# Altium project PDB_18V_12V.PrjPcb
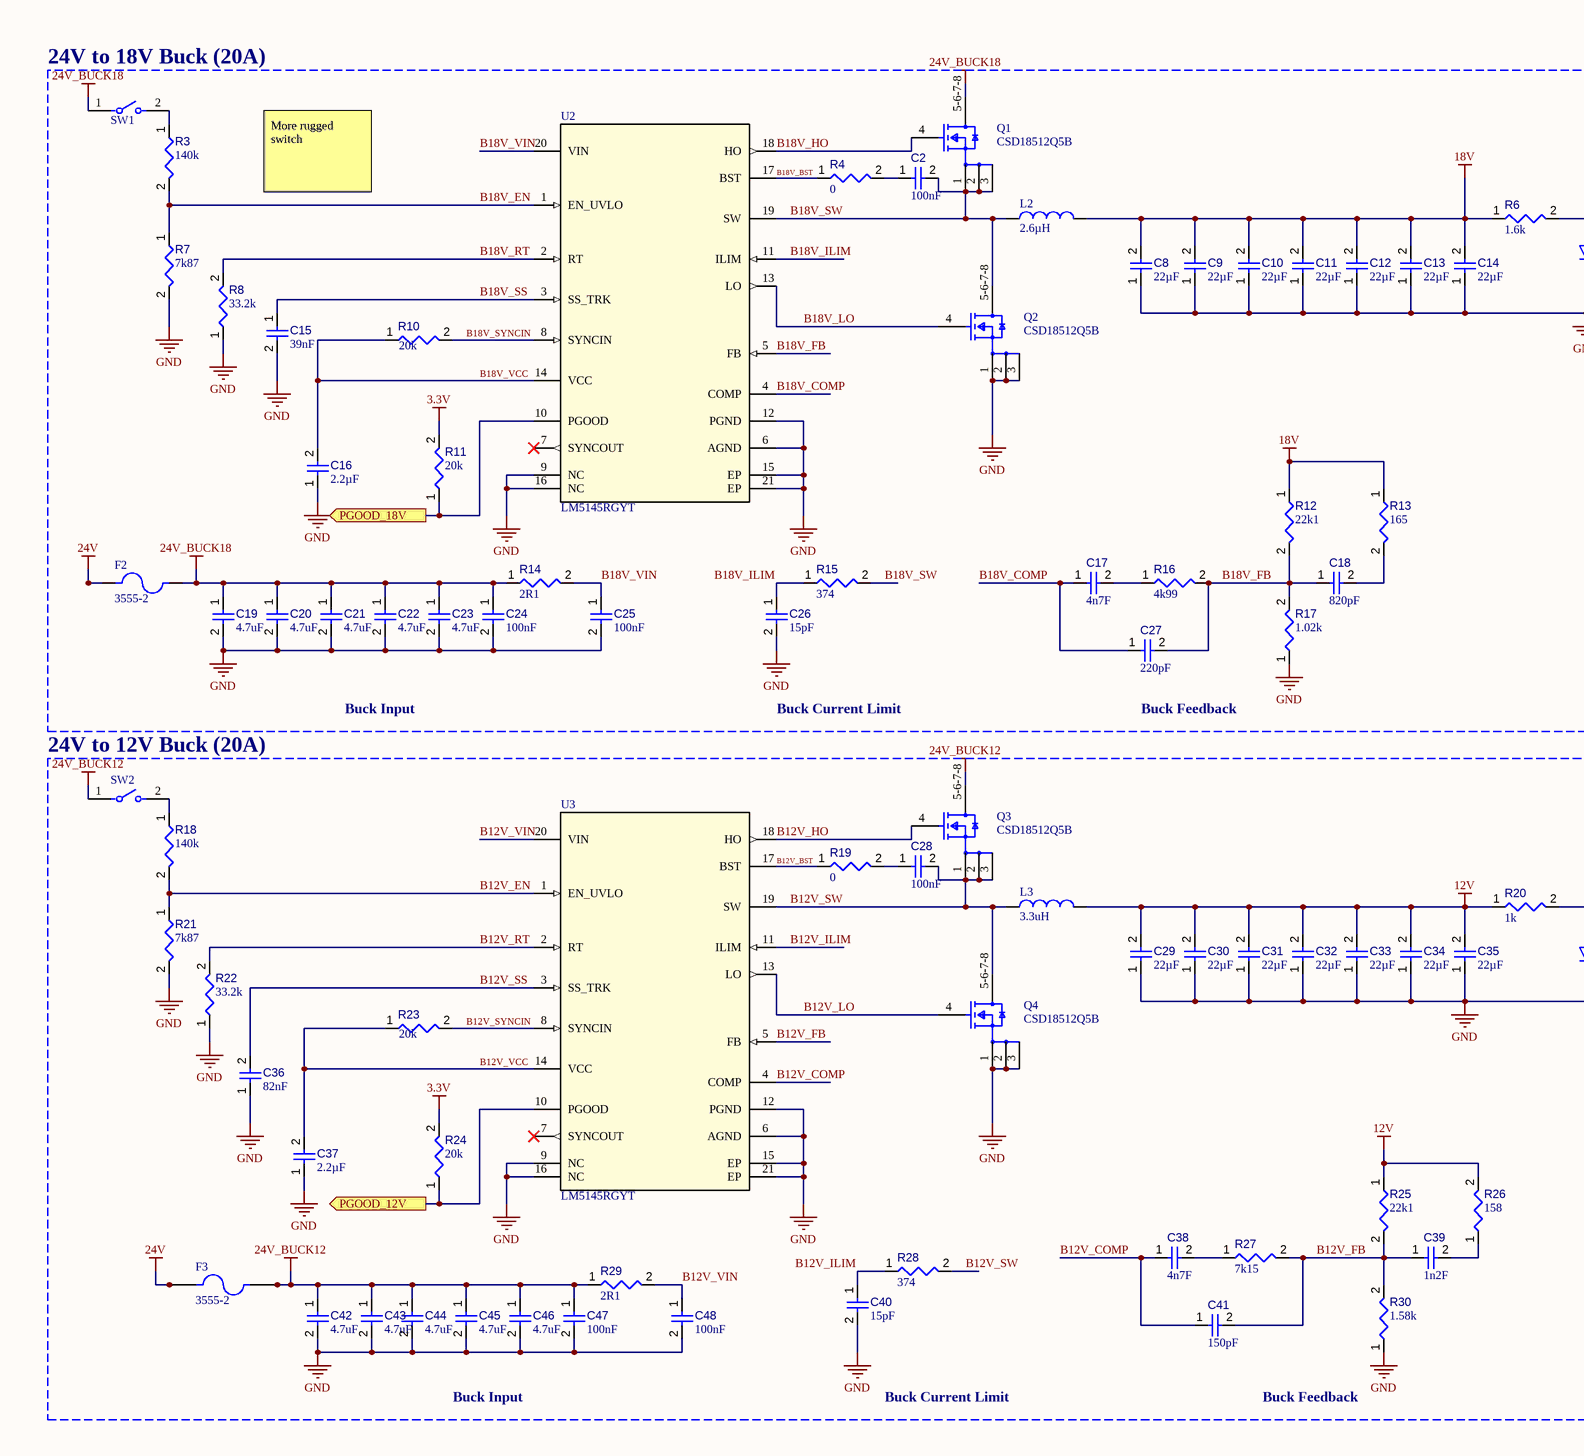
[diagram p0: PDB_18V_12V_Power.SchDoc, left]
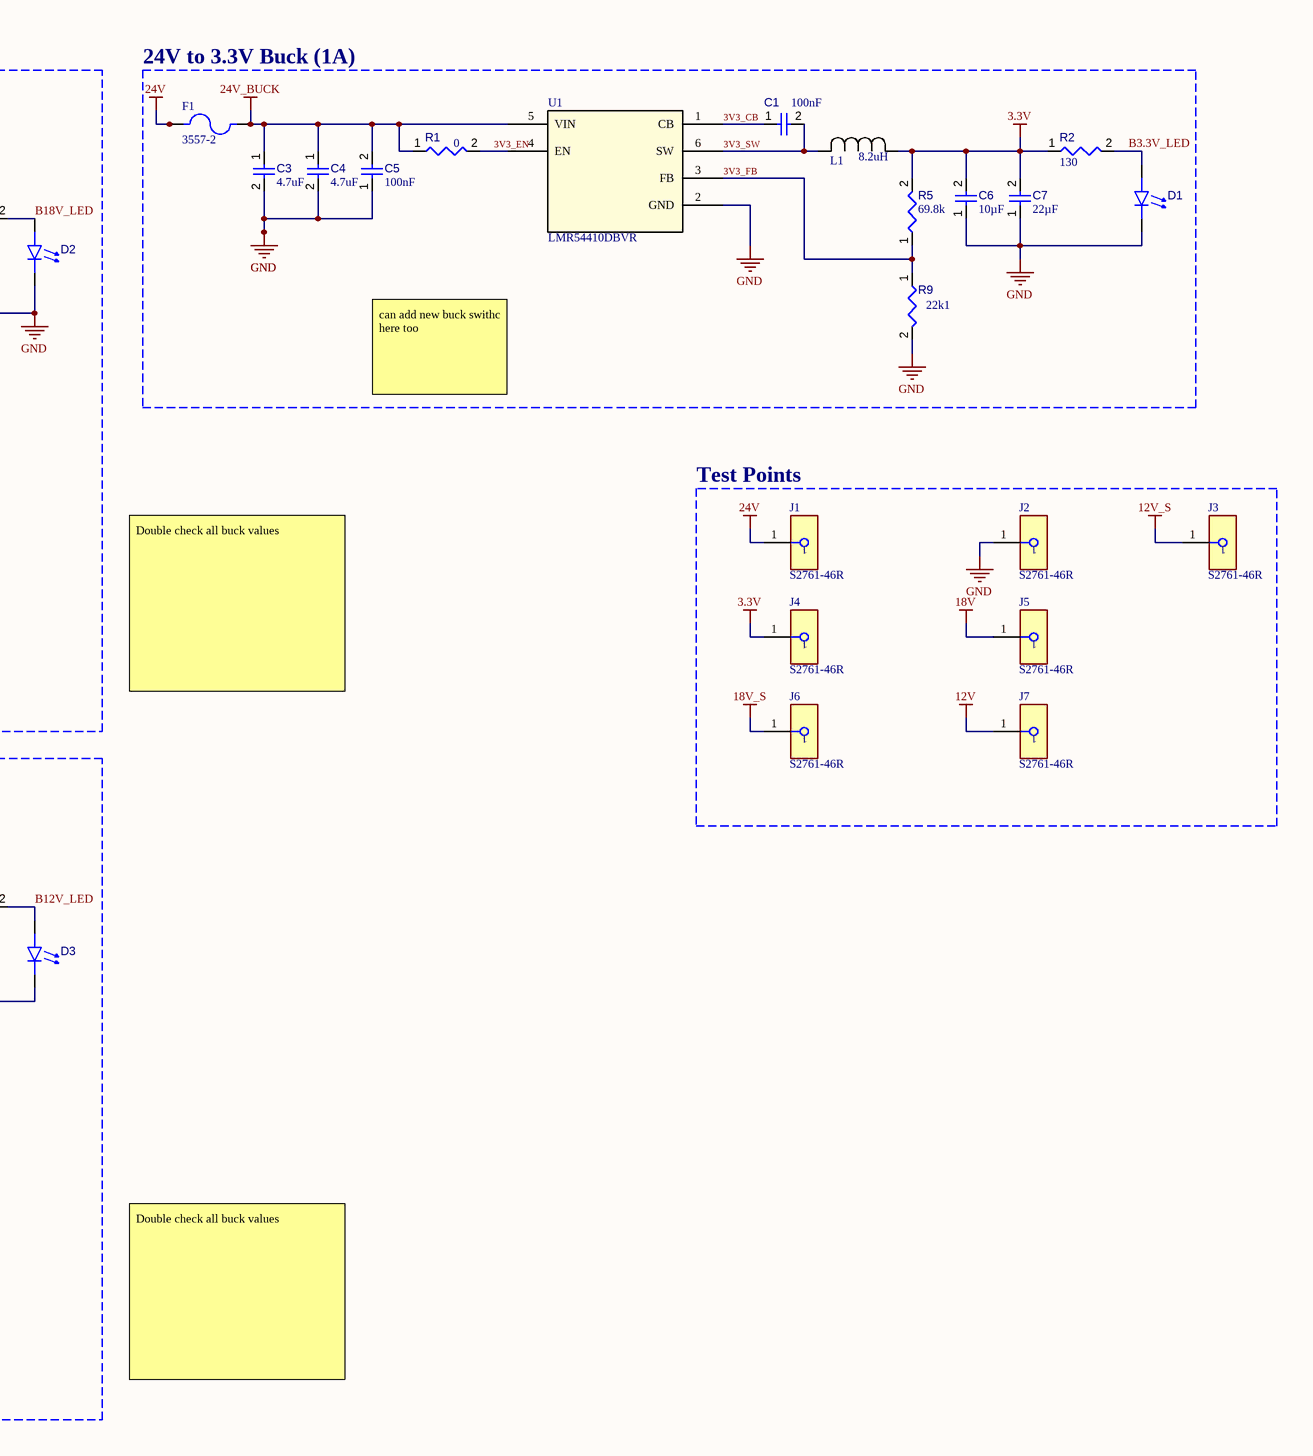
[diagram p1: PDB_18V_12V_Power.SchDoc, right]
3 sheets, 209 parts. Net scope: flat (ports and power ports of the same name join across sheets).
Board file: PDB_18V_12V.PcbDoc
Sheets:
  PDB_18V_12V_Power.SchDoc
  PDB_18V_12V_Connectors.SchDoc
  PDB_18V_12V_MCU_Peripherals.SchDoc

## Sheet PDB_18V_12V_Power.SchDoc
size A2

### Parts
C1  value 100nF  [FP-CGA3E-0_3-0_1-MFG]  (hidden comment: CGA3E3X8R1H104K080AB)
C2  value 100nF  [FP-CGA3E-0_3-0_1-MFG]  (hidden comment: CGA3E3X8R1H104K080AB)
C3  value 4.7uF  [FP-1210-L_3_3_0_4-W_2_5_0-IPC_A]  (hidden comment: 12105C475KAT2A)
C4  value 4.7uF  [FP-1210-L_3_3_0_4-W_2_5_0-IPC_A]  (hidden comment: 12105C475KAT2A)
C5  value 100nF  [FP-CGA3E-0_3-0_1-MFG]  (hidden comment: CGA3E3X8R1H104K080AB)
C6  value 10µF  [TAYO-C1210-2_M]  (hidden comment: UMK325BJ106MM-T)
C7  value 22µF  [FP-GRM32-MFG]  (hidden comment: GRM32ER61E226KE15L)
C8  value 22µF  [FP-GRM32-MFG]  (hidden comment: GRM32ER61E226KE15L)
C9  value 22µF  [FP-GRM32-MFG]  (hidden comment: GRM32ER61E226KE15L)
C10  value 22µF  [FP-GRM32-MFG]  (hidden comment: GRM32ER61E226KE15L)
C11  value 22µF  [FP-GRM32-MFG]  (hidden comment: GRM32ER61E226KE15L)
C12  value 22µF  [FP-GRM32-MFG]  (hidden comment: GRM32ER61E226KE15L)
C13  value 22µF  [FP-GRM32-MFG]  (hidden comment: GRM32ER61E226KE15L)
C14  value 22µF  [FP-GRM32-MFG]  (hidden comment: GRM32ER61E226KE15L)
C15  value 39nF  [FP-GCJ188-0_2-MFG]  (hidden comment: GCJ188R71C393KA01J)
C16  value 2.2µF  [FP-GRM188-0_1-e0_2_0_5-IPC_B]  (hidden comment: GRM188R6YA225KA12D)
C17  value 4n7F  [FP-C0603C-CF-IPC_B]  (hidden comment: C0603C472J5RACTU)
C18  value 820pF  [FP-C0603C-CF-MFG]  (hidden comment: C0603C821K5RACTU)
C19  value 4.7uF  [FP-1210-L_3_3_0_4-W_2_5_0-IPC_A]  (hidden comment: 12105C475KAT2A)
C20  value 4.7uF  [FP-1210-L_3_3_0_4-W_2_5_0-IPC_A]  (hidden comment: 12105C475KAT2A)
C21  value 4.7uF  [FP-1210-L_3_3_0_4-W_2_5_0-IPC_A]  (hidden comment: 12105C475KAT2A)
C22  value 4.7uF  [FP-1210-L_3_3_0_4-W_2_5_0-IPC_A]  (hidden comment: 12105C475KAT2A)
C23  value 4.7uF  [FP-1210-L_3_3_0_4-W_2_5_0-IPC_A]  (hidden comment: 12105C475KAT2A)
C24  value 100nF  [FP-CGA3E-0_3-0_1-MFG]  (hidden comment: CGA3E3X8R1H104K080AB)
C25  value 100nF  [FP-CGA3E-0_3-0_1-MFG]  (hidden comment: CGA3E3X8R1H104K080AB)
C26  value 15pF  [FP-0603-L_1_6_0_15-W_0_81-IPC_C]  (hidden comment: 06035A150JAT2A)
C27  value 220pF  [FP-0603-L_1_6_0_15-W_0_81-IPC_C]  (hidden comment: 06035C221KAT2A)
C28  value 100nF  [FP-CGA3E-0_3-0_1-MFG]  (hidden comment: CGA3E3X8R1H104K080AB)
C29  value 22µF  [FP-GRM32-MFG]  (hidden comment: GRM32ER61E226KE15L)
C30  value 22µF  [FP-GRM32-MFG]  (hidden comment: GRM32ER61E226KE15L)
C31  value 22µF  [FP-GRM32-MFG]  (hidden comment: GRM32ER61E226KE15L)
C32  value 22µF  [FP-GRM32-MFG]  (hidden comment: GRM32ER61E226KE15L)
C33  value 22µF  [FP-GRM32-MFG]  (hidden comment: GRM32ER61E226KE15L)
C34  value 22µF  [FP-GRM32-MFG]  (hidden comment: GRM32ER61E226KE15L)
C35  value 22µF  [FP-GRM32-MFG]  (hidden comment: GRM32ER61E226KE15L)
C36  value 82nF  [FP-GCM188-0_1-MFG]  (hidden comment: GCM188L81H823KA57J)
C37  value 2.2µF  [FP-GRM188-0_1-e0_2_0_5-IPC_B]  (hidden comment: GRM188R6YA225KA12D)
C38  value 4n7F  [FP-C0603C-CF-IPC_B]  (hidden comment: C0603C472J5RACTU)
C39  value 1n2F  [FP-CC0603-DA-IPC_B]  (hidden comment: CC0603KRX7R9BB122)
C40  value 15pF  [FP-0603-L_1_6_0_15-W_0_81-IPC_C]  (hidden comment: 06035A150JAT2A)
C41  value 150pF  [CAPC1608X90X35LL15T15]  (hidden comment: C0603C151J5GACTU)
C42  value 4.7uF  [FP-1210-L_3_3_0_4-W_2_5_0-IPC_A]  (hidden comment: 12105C475KAT2A)
C43  value 4.7uF  [FP-1210-L_3_3_0_4-W_2_5_0-IPC_A]  (hidden comment: 12105C475KAT2A)
C44  value 4.7uF  [FP-1210-L_3_3_0_4-W_2_5_0-IPC_A]  (hidden comment: 12105C475KAT2A)
C45  value 4.7uF  [FP-1210-L_3_3_0_4-W_2_5_0-IPC_A]  (hidden comment: 12105C475KAT2A)
C46  value 4.7uF  [FP-1210-L_3_3_0_4-W_2_5_0-IPC_A]  (hidden comment: 12105C475KAT2A)
C47  value 100nF  [FP-CGA3E-0_3-0_1-MFG]  (hidden comment: CGA3E3X8R1H104K080AB)
C48  value 100nF  [FP-CGA3E-0_3-0_1-MFG]  (hidden comment: CGA3E3X8R1H104K080AB)
D1  150120VS75000  [WL-SMCW_1206_150120xx75000]  (value not drawn)
D2  150120VS75000  [WL-SMCW_1206_150120xx75000]  (value not drawn)
D3  150120VS75000  [WL-SMCW_1206_150120xx75000]  (value not drawn)
F1  3557-2  [FUSE_3557-2]
F2  3555-2  [FUSE_3555-2]
F3  3555-2  [FUSE_3555-2]
J1  S2761-46R  [FP-S2761-46R-MFG]
J2  S2761-46R  [FP-S2761-46R-MFG]
J3  S2761-46R  [FP-S2761-46R-MFG]
J4  S2761-46R  [FP-S2761-46R-MFG]
J5  S2761-46R  [FP-S2761-46R-MFG]
J6  S2761-46R  [FP-S2761-46R-MFG]
J7  S2761-46R  [FP-S2761-46R-MFG]
L1  value 8.2uH  [IND_BOURNS_SRN6045]  (hidden comment: SRN6045-8R2Y)
L2  value 2.6µH  [WE-HCI_1890]  (hidden comment: 7443556260)
L3  value 3.3uH  [FP-IHLP-6767GZ-FP_3_825x1-MFG]  (hidden comment: IHLP6767GZER3R3M01)
Q1  CSD18512Q5B  [FP-DNK0008A-MFG]
Q2  CSD18512Q5B  [FP-DNK0008A-MFG]
Q3  CSD18512Q5B  [FP-DNK0008A-MFG]
Q4  CSD18512Q5B  [FP-DNK0008A-MFG]
R1  value 0  [FP-RMCF0603-IPC_A]  (hidden comment: RMCF0603ZT0R00)
R2  value 130  [FP-AC0603-MFG]  (hidden comment: AC0603FR-07130RL)
R3  value 140k  [RESC1608X55X30LL15T15]  (hidden comment: ERJ-3EKF1403V)
R4  value 0  [FP-RMCF0603-IPC_A]  (hidden comment: RMCF0603ZT0R00)
R5  value 69.8k  [FP-CRCW0603-e3-MFG]  (hidden comment: CRCW060369K8FKEB)
R6  value 1.6k  [FP-RMCF0603-MFG]  (hidden comment: RMCF0603JT1K60)
R7  value 7k87  [RESC1608X55X30NL20T20]  (hidden comment: ERA-3AEB7871V)
R8  value 33.2k  [RESC1608X55X25ML10T15]  (hidden comment: RC0603FR-0733K2L)
R9  value 22k1  [FP-RMCF0603-MFG]  (hidden comment: RMCF0603FT22K1)
R10  value 20k  [FP-RC0603-0_55-IPC_C]  (hidden comment: RC0603FR-0720KL)
R11  value 20k  [FP-RC0603-0_55-IPC_C]  (hidden comment: RC0603FR-0720KL)
R12  value 22k1  [FP-RMCF0603-MFG]  (hidden comment: RMCF0603FT22K1)
R13  value 165  [RESC1608X55X30LL15T15]  (hidden comment: ERJ-3EKF1650V)
R14  value 2R1  [FP-CRCW0603-e3-MFG]  (hidden comment: CRCW06032R10FKEA)
R15  value 374  [RESC1608X55X25LL10T15]  (hidden comment: RC0603FR-07374RL)
R16  value 4k99  [FP-RT0603-IPC_C]  (hidden comment: RT0603DRD074K99L)
R17  value 1.02k  [RESC1609X50X30LL10T20]  (hidden comment: CRCW06031K02FKEA)
R18  value 140k  [RESC1608X55X30LL15T15]  (hidden comment: ERJ-3EKF1403V)
R19  value 0  [FP-RMCF0603-IPC_A]  (hidden comment: RMCF0603ZT0R00)
R20  value 1k  [RESC1608X55X25ML10T15]  (hidden comment: RT0603BRE071KL)
R21  value 7k87  [RESC1608X55X30NL20T20]  (hidden comment: ERA-3AEB7871V)
R22  value 33.2k  [RESC1608X55X25ML10T15]  (hidden comment: RC0603FR-0733K2L)
R23  value 20k  [FP-RC0603-0_55-IPC_C]  (hidden comment: RC0603FR-0720KL)
R24  value 20k  [FP-RC0603-0_55-IPC_C]  (hidden comment: RC0603FR-0720KL)
R25  value 22k1  [FP-RMCF0603-MFG]  (hidden comment: RMCF0603FT22K1)
R26  value 158  [RESC1608X55X25LL10T15]  (hidden comment: RC0603FR-07158RL)
R27  value 7k15  [FP-CRCW0603-HPe3-MFG]  (hidden comment: CRCW06037K15FKEAHP)
R28  value 374  [RESC1608X55X25LL10T15]  (hidden comment: RC0603FR-07374RL)
R29  value 2R1  [FP-CRCW0603-e3-MFG]  (hidden comment: CRCW06032R10FKEA)
R30  value 1.58k  [RESC1609X50X30LL10T20]  (hidden comment: CRCW06031K58FKEA)
SW1  SDA01H1SBD  [FP-SDA01H1SBD-MFG]  (value not drawn)
SW2  SDA01H1SBD  [FP-SDA01H1SBD-MFG]  (value not drawn)
U1  LMR54410DBVR  [SOT-23-6-DBV_TEX]
U2  LM5145RGYT  [RGY0020B]
U3  LM5145RGYT  [RGY0020B]

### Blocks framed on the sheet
24V to 18V Buck (20A): C2 C8-C27 D2 F2 L2 Q1 Q2 R3 R4 R6-R8 R10-R17 SW1 U2
24V to 3.3V Buck (1A): C1 C3-C7 D1 F1 L1 R1 R2 R5 R9 U1
Test Points: J1-J7
24V to 12V Buck (20A): C28-C48 D3 F3 L3 Q3 Q4 R18-R30 SW2 U3

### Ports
PGOOD_12V (out), PGOOD_18V (out)

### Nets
3.3V: C6.2 C7.2 J4.1 L1.1 R2.1 R5.2 R11.2 R24.2
12V: C29.2 C30.2 C31.2 C32.2 C33.2 C34.2 C35.2 J7.1 L3.2 R20.1 R25.1 R26.2
12V_S: J3.1
18V: C8.2 C9.2 C10.2 C11.2 C12.2 C13.2 C14.2 J5.1 L2.2 R6.1 R12.1 R13.1
18V_S: J6.1
24V: F1.1_1 F1.1_2 F2.1_1 F2.1_2 F3.1_1 F3.1_2 J1.1
24V_BUCK: C3.1 C4.1 C5.2 F1.2_1 F1.2_2 R1.1 U1.5(VIN)
24V_BUCK12: C42.1 C43.1 C44.1 C45.1 C46.1 C47.1 F3.2_1 F3.2_2 Q3.5-6-7-8(D) R29.1 SW2.1
24V_BUCK18: C19.1 C20.1 C21.1 C22.1 C23.1 C24.1 F2.2_1 F2.2_2 Q1.5-6-7-8(D) R14.1 SW1.1
GND: C3.2 C4.2 C5.1 C6.1 C7.1 C8.1 C9.1 C10.1 C11.1 C12.1 C13.1 C14.1 C15.2 C16.1 C19.2 C20.2 C21.2 C22.2 C23.2 C24.2 C25.2 C26.2 C29.1 C30.1 C31.1 C32.1 C33.1 C34.1 C35.1 C36.1 C37.1 C40.2 C42.2 C43.2 C44.2 C45.2 C46.2 C47.2 C48.2 D1.1(K) D2.1(K) D3.1(K) J2.1 Q2.1(S) Q2.2(S) Q2.3(S) Q4.1(S) Q4.2(S) Q4.3(S) R7.2 R8.1 R9.2 R17.1 R21.2 R22.1 R30.1 U1.2(GND) U2.6(AGND) U2.9(NC) U2.12(PGND) U2.15(EP) U2.16(NC) U2.21(EP) U3.6(AGND) U3.9(NC) U3.12(PGND) U3.15(EP) U3.16(NC) U3.21(EP)
3V3_CB: C1.1 U1.1(CB)
3V3_EN: R1.2 U1.4(EN)
3V3_FB: R5.1 R9.1 U1.3(FB)
3V3_SW: C1.2 L1.2 U1.6(SW)
B3.3V_LED: D1.2(A) R2.2
B12V_BST: R19.1 U3.17(BST)
B12V_COMP: C38.1 C41.1 U3.4(COMP)
B12V_EN: R18.2 R21.1 U3.1(EN_UVLO)
B12V_FB: C39.1 C41.2 R25.2 R27.2 R30.2 U3.5(FB)
B12V_HO: Q3.4(G) U3.18(HO)
B12V_ILIM: C40.1 R28.1 U3.11(ILIM)
B12V_LED: D3.2(A) R20.2
B12V_LO: Q4.4(G) U3.13(LO)
B12V_RT: R22.2 U3.2(RT)
B12V_SS: C36.2 U3.3(SS_TRK)
B12V_SW: C28.2 L3.1 Q3.1(S) Q3.2(S) Q3.3(S) Q4.5-6-7-8(D) R28.2 U3.19(SW)
B12V_SYNCIN: R23.2 U3.8(SYNCIN)
B12V_VCC: C37.2 R23.1 U3.14(VCC)
B12V_VIN: C48.1 R29.2 U3.20(VIN)
B18V_BST: R4.1 U2.17(BST)
B18V_COMP: C17.1 C27.1 U2.4(COMP)
B18V_EN: R3.2 R7.1 U2.1(EN_UVLO)
B18V_FB: C18.1 C27.2 R12.2 R16.2 R17.2 U2.5(FB)
B18V_HO: Q1.4(G) U2.18(HO)
B18V_ILIM: C26.1 R15.1 U2.11(ILIM)
B18V_LED: D2.2(A) R6.2
B18V_LO: Q2.4(G) U2.13(LO)
B18V_RT: R8.2 U2.2(RT)
B18V_SS: C15.1 U2.3(SS_TRK)
B18V_SW: C2.2 L2.1 Q1.1(S) Q1.2(S) Q1.3(S) Q2.5-6-7-8(D) R15.2 U2.19(SW)
B18V_SYNCIN: R10.2 U2.8(SYNCIN)
B18V_VCC: C16.2 R10.1 U2.14(VCC)
B18V_VIN: C25.1 R14.2 U2.20(VIN)
PGOOD_12V: R24.1 U3.10(PGOOD) ; port PGOOD_12V
PGOOD_18V: R11.1 U2.10(PGOOD) ; port PGOOD_18V
NetC2_1: C2.1 R4.2
NetC17_2: C17.2 R16.1
NetC18_2: C18.2 R13.2
NetC28_1: C28.1 R19.2
NetC38_2: C38.2 R27.1
NetC39_2: C39.2 R26.1
NetR3_1: R3.1 SW1.2
NetR18_1: R18.1 SW2.2

Not connected (* = marked no-connect by the designer): U2 7(SYNCOUT)*; U3 7(SYNCOUT)*

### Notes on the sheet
- More rugged switch
- can add new buck swithc here too
- Buck Input
- Buck Current Limit
- Buck Feedback
- Double check all buck values

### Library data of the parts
C1 C2 C5 C24 C25 C28 C47 C48 = CMP-001-00163-1: CGA Series 0603 0.1 uF 50 V ±10% Tolerance X8R Multilayer Ceramic Capacitor; Voltage Rating: 50V
C3 C4 C19-C23 C42-C46 = CMP-001-00137-1: Ceramic Capacitor, Multilayer, Ceramic, 50V, 10% +Tol, 10% -Tol, X7R, 15% TC, 4.7uF, Surface Mount, 1210
C6 = CMP-001-00183-1: 50V 10uF X5R ±20% 1210 Multilayer Ceramic Capacitors MLCC - SMD/SMT ROHS
C7-C14 C29-C35 = CMP-001-00168-1: 25V 22uF X5R ±10% 1210 Multilayer Ceramic Capacitors MLCC - SMD/SMT ROHS
C15 = CMP-001-00170-1: Ceramic Capacitor, YES, Ceramic, 16V, 10% +Tol, 10% -Tol, X7R, 15% TC, 0.039uF, Surface Mount, 1608M/0603
C16 C37 = CMP-001-00153-1: Ceramic Capacitor, Multilayer, Ceramic, 35V, 10% +Tol, 10% -Tol, X5R, 15% TC, 2.2uF, Surface Mount, 0603
C17 C38 = CMP-001-00143-1: Ceramic Capacitor, Multilayer, Ceramic, 50V, 5% +Tol, 5% -Tol, X7R, 15% TC, 0.0047uF, Surface Mount, 0603
C18 = CMP-001-00171-1: C0603C 820PF Ceramic Multilayer Capacitor, 50 VDC, +125DEGC, X7R Dielec, +/-10%; Voltage Rating: 50V; Tolerance: 10%
C26 C40 = CMP-001-00146-1: Ceramic Capacitor, Multilayer, Ceramic, 50V, 5% +Tol, 5% -Tol, C0G, 30ppm/Cel TC, 0.000015uF, Surface Mount, 0603
C27 = CMP-001-00148-1: Ceramic Capacitor, Multilayer, Ceramic, 50V, 10% +Tol, 10% -Tol, X7R, 15% TC, 0.00022uF, Surface Mount, 0603
C36 = CMP-001-00182-1: Ceramic Capacitor, YES, Ceramic, 50V, 10% +Tol, 10% -Tol, X8L, -40/+15% TC, 0.082uF, Surface Mount, 1608M/0603
C39 = CMP-001-00145-1: Ceramic Capacitor, Multilayer, Ceramic, 50V, 10% +Tol, 10% -Tol, X7R, 15% TC, 0.0012uF, Surface Mount, 0603
C41 = CMP-001-00144-1: Ceramic Capacitor, Multilayer, Ceramic, 50V, 5% +Tol, 5% -Tol, C0G, 30ppm/Cel TC, 0.00015uF, Surface Mount, 0603
D1-D3 = CMP-007-00044-1: Single Color LED, Bright Green, Water Clear, 2mm; Forward Current: 30mA
F1 = CMP-005-00014-1: THM 2 in 1 Auto Blade Holder; MF: Keystone Electronics
F2 F3 = CMP-005-00015-2: Auto Fuse Holder, 1 Fuse, Blade, Standard, THM, 50Amp, Hi-Temp Nylon, UL94V-0; MF: Keystone Electronics
J1-J7 = CMP-002-00083-1: Interconnection Device
L1 = CMP-006-00036-1: Description; Manufacturer_Name: Bourns Electronics
L2 = CMP-006-00034-1: WE-HCI SMT Flat Wire High Current Inductor; Tolerance: 20%; Current Rating: 31.5A; Self Resonant Frequency: 42MHz
L3 = CMP-006-00032-1: Inductor High Current Shielded Wirewound 3.3uH 20% 100KHz 28A 3.88mOhm DCR 6767 T/R
Q1-Q4 = CMP-013-00041-1: 40-V, N channel NexFET™ power MOSFET, single SON 5 mm x 6 mm, 1.6 mOhm 8-VSON-CLIP -55 to 150
R1 R4 R19 = CMP-009-00236-1: Fixed Resistor, Metal Glaze/thick Film, 0.1W, 0ohm, Surface Mount, 0603; Power: 100mW
R2 = CMP-009-00292-1: Res Thick Film 0603 130 Ohm 1% 0.1W(1/10W) ±100ppm/C Pad SMD T/R Automotive AEC-Q200; Voltage Rating: 75V
R3 R18 = CMP-009-00259-1: Fixed Resistor, Metal Glaze/thick Film, 0.1W, 140000ohm, 75V, 1% +/-Tol, 100ppm/Cel, Surface Mount, 0603; Power: 100mW
R5 = CMP-009-00297-1: CRCW FIXED RESISTOR 0603 (1608Metric) Chip Resistor ±1% ±100ppm/C 69.8kOhm 0.1W 1/10W; Voltage Rating: 75V
R6 = CMP-009-00285-1: Res Thick Film 0603 1.6K Ohm 5% 1/10W ±200ppm/°C Molded SMD Paper T/R; Voltage Rating: 75V
R7 R21 = CMP-009-00260-1: Fixed Resistor, Thin Film, 0.1W, 7870ohm, 75V, 0.1% +/-Tol, 25ppm/Cel, Surface Mount, 0603; Power: 100mW
R8 R22 = CMP-009-00279-1: 100mW Thick Film Resistors 75V ±100ppm/℃ ±1% 33.2kΩ 0603 Chip Resistor - Surface Mount ROHS
R9 R12 R25 = CMP-009-00240-1: Fixed Resistor, Metal Glaze/thick Film, 0.1W, 22100ohm, 75V, 1% +/-Tol, 100ppm/Cel, Surface Mount, 0603; Power: 100mW
R10 R11 R23 R24 = CMP-009-00212-1: Fixed Resistor, Metal Glaze/thick Film, 0.1W, 20000ohm, 75V, 1% +/-Tol, 100ppm/Cel, Surface Mount, 0603; Power: 100mW
R13 = CMP-009-00251-1: Fixed Resistor, Metal Glaze/thick Film, 0.1W, 165ohm, 75V, 1% +/-Tol, 100ppm/Cel, Surface Mount, 0603; Power: 100mW
R14 R29 = CMP-009-00275-1: Res Thick Film 0603 2.1 Ohm 1% 0.1W(1/10W) ±100ppm/C Molded SMD Automotive Paper T/R; Voltage Rating: 75V
R15 R28 = CMP-009-00283-1: Res Thick Film 0603 374 Ohm 1% 0.1W(1/10W) ±100ppm/C Pad SMD T/R; Voltage Rating: 75V
R16 = CMP-009-00250-1: Fixed Resistor, Thin Film, 0.1W, 4990ohm, 75V, 0.5% +/-Tol, 25ppm/Cel, Surface Mount, 0603; Power: 100mW
R17 = CMP-009-00284-1: Res Thick Film 0603 1.02K Ohm 1% 1/10W ±100ppm/°C Molded SMD SMD Paper T/R; Voltage Rating: 75V
R20 = CMP-009-00263-1: Fixed Resistor, Thin Film, 0.1W, 1000ohm, 75V, 0.1% +/-Tol, 50ppm/Cel, Surface Mount, 0603; Power: 100mW
R26 = CMP-009-00287-1: Res Thick Film 0603 158 Ohm 1% 0.1W(1/10W) ±100ppm/C Pad SMD T/R; Voltage Rating: 75V
R27 = CMP-009-00197-1: Fixed Resistor, Metal Glaze/thick Film, 0.33W, 7150ohm, 75V, 1% +/-Tol, 100ppm/Cel, Surface Mount, 0603; Power: 250mW
R30 = CMP-009-00286-1: Fixed Resistor, Metal Glaze/Thick Film, 0.1W, 1580ohm, 75V, 1% +/-Tol, Surface Mount, 0603
SW1 SW2 = CMP-011-00016-1: Slide Dip Switch, 1 Switches, SPST, Latched, 0.1A, 50VDC, Solder Terminal, Surface Mount-straight
U1 = CMP-00030-00008-3: 4V to 36V, 1A, 80-ÂµA Iq synchronous SIMPLE SWITCHERÂ® power converter 6-SOT-23 -40 to 125; Manufacturer_Name: Texas Instruments
U2 U3 = CMP-049-000000-3: 75V Synchronous Buck Controller With Wide Input Voltage and Duty Cycle Ranges 20-VQFN -40 to 125; Manufacturer_Name: Texas Instruments

## Sheet PDB_18V_12V_Connectors.SchDoc
size A3
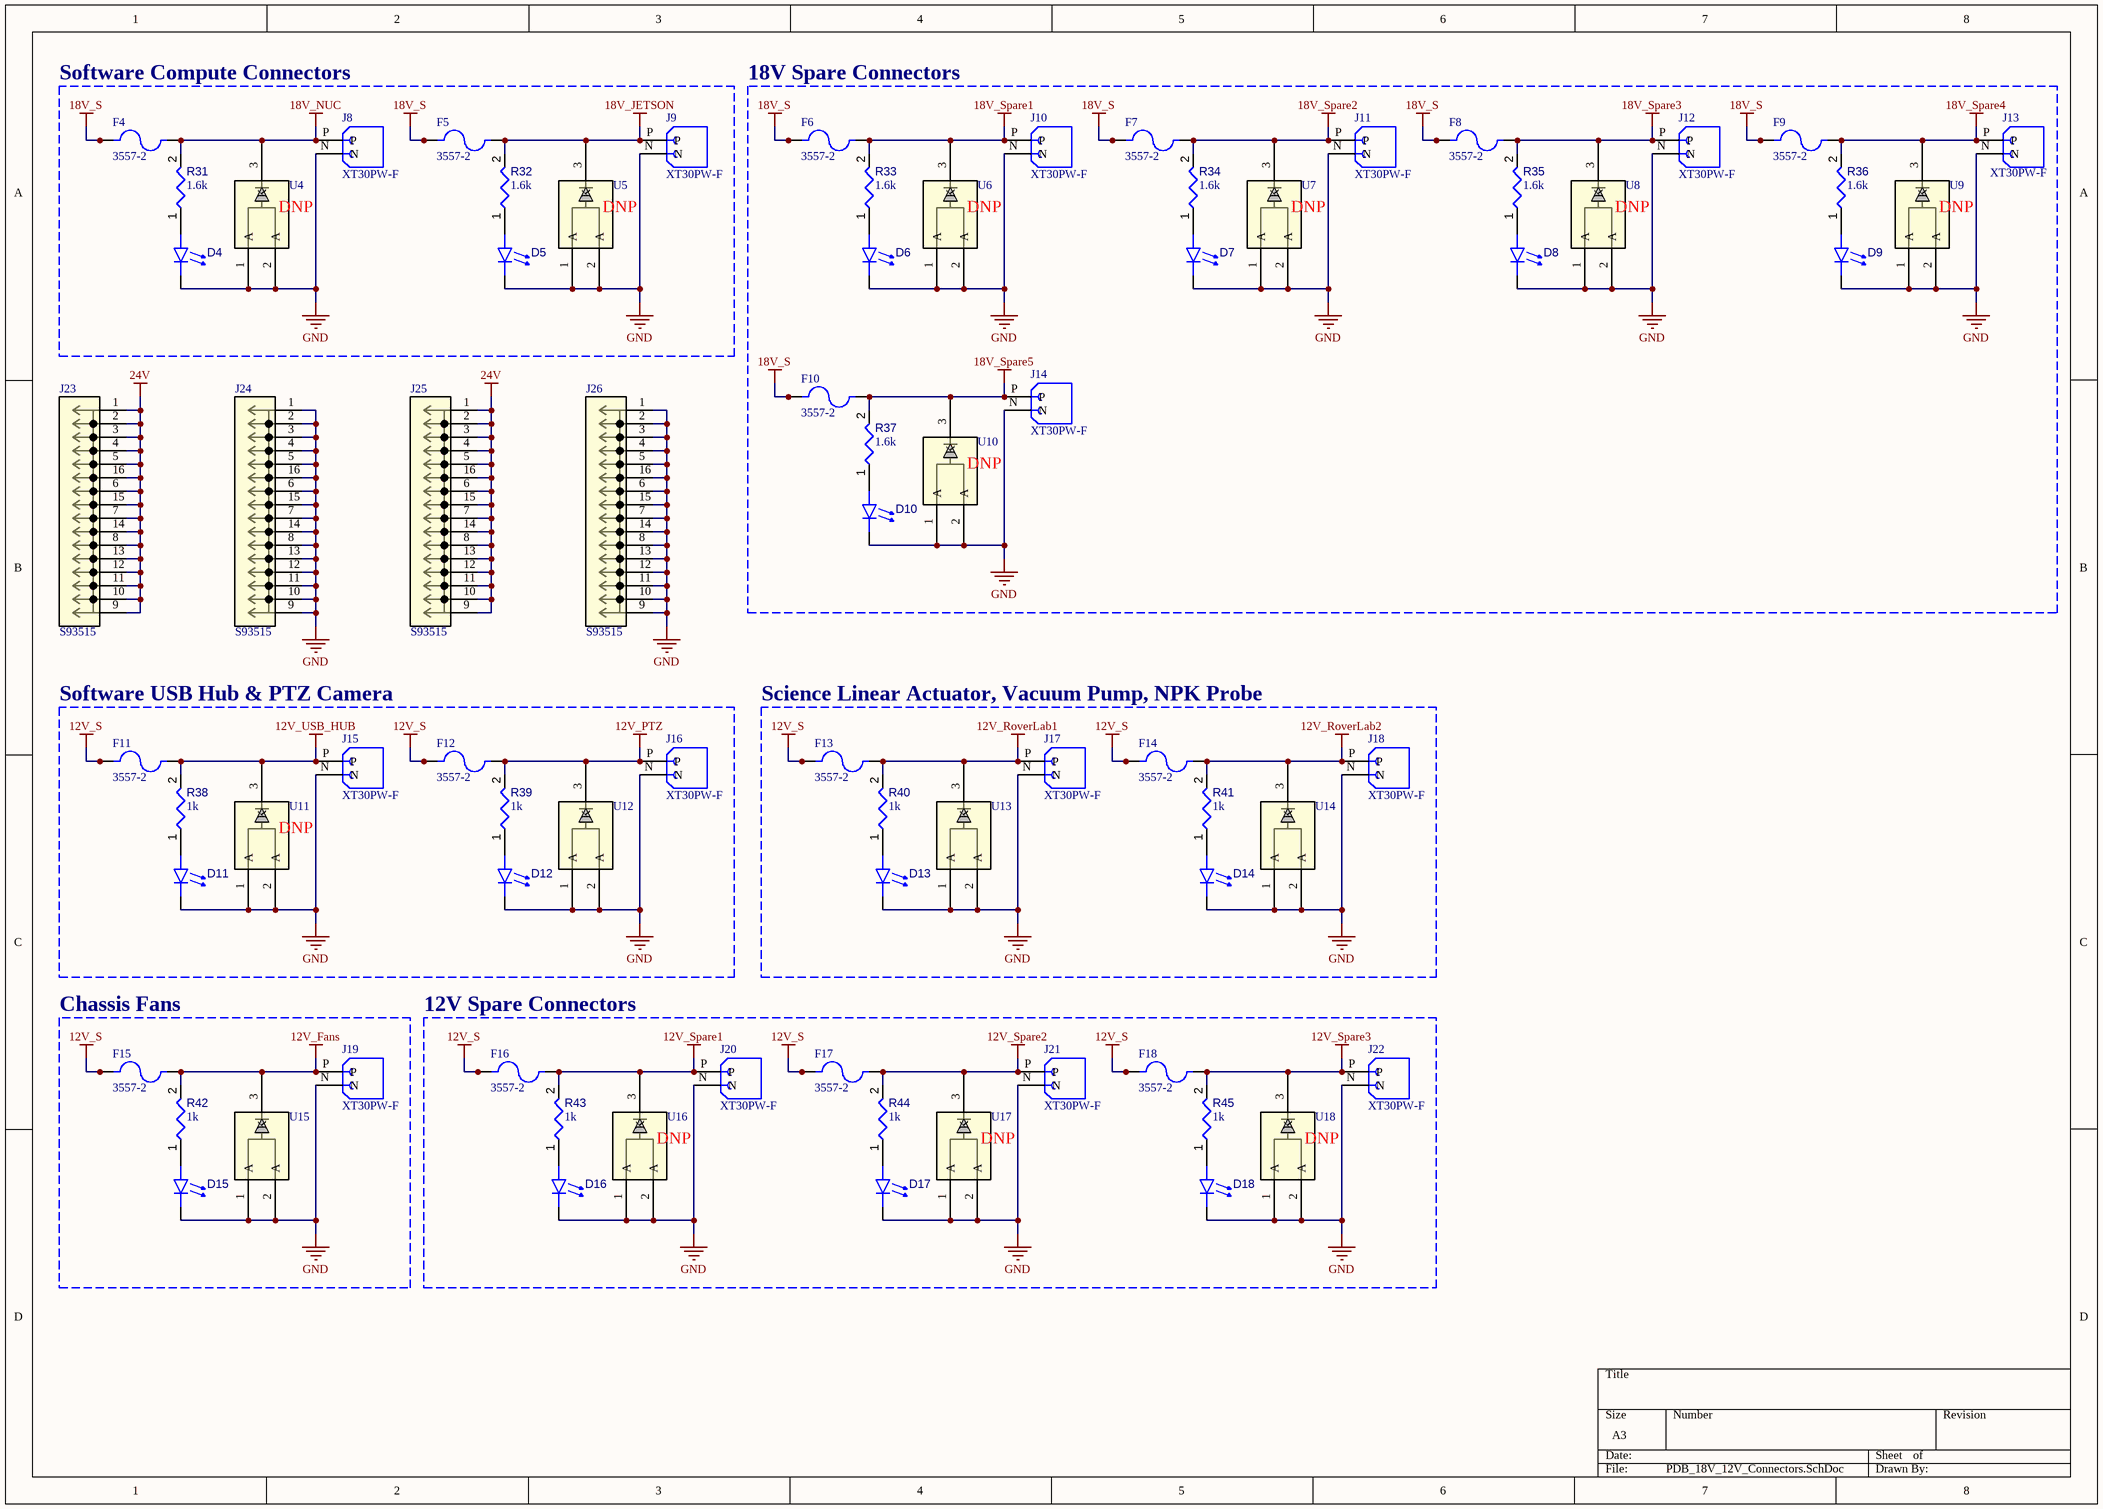
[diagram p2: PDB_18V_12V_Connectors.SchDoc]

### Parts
D4  150120VS75000  [WL-SMCW_1206_150120xx75000]  (value not drawn)
D5  150120VS75000  [WL-SMCW_1206_150120xx75000]  (value not drawn)
D6  150120VS75000  [WL-SMCW_1206_150120xx75000]  (value not drawn)
D7  150120VS75000  [WL-SMCW_1206_150120xx75000]  (value not drawn)
D8  150120VS75000  [WL-SMCW_1206_150120xx75000]  (value not drawn)
D9  150120VS75000  [WL-SMCW_1206_150120xx75000]  (value not drawn)
D10  150120VS75000  [WL-SMCW_1206_150120xx75000]  (value not drawn)
D11  150120VS75000  [WL-SMCW_1206_150120xx75000]  (value not drawn)
D12  150120VS75000  [WL-SMCW_1206_150120xx75000]  (value not drawn)
D13  150120VS75000  [WL-SMCW_1206_150120xx75000]  (value not drawn)
D14  150120VS75000  [WL-SMCW_1206_150120xx75000]  (value not drawn)
D15  150120VS75000  [WL-SMCW_1206_150120xx75000]  (value not drawn)
D16  150120VS75000  [WL-SMCW_1206_150120xx75000]  (value not drawn)
D17  150120VS75000  [WL-SMCW_1206_150120xx75000]  (value not drawn)
D18  150120VS75000  [WL-SMCW_1206_150120xx75000]  (value not drawn)
F4  3557-2  [FUSE_3557-2]
F5  3557-2  [FUSE_3557-2]
F6  3557-2  [FUSE_3557-2]
F7  3557-2  [FUSE_3557-2]
F8  3557-2  [FUSE_3557-2]
F9  3557-2  [FUSE_3557-2]
F10  3557-2  [FUSE_3557-2]
F11  3557-2  [FUSE_3557-2]
F12  3557-2  [FUSE_3557-2]
F13  3557-2  [FUSE_3557-2]
F14  3557-2  [FUSE_3557-2]
F15  3557-2  [FUSE_3557-2]
F16  3557-2  [FUSE_3557-2]
F17  3557-2  [FUSE_3557-2]
F18  3557-2  [FUSE_3557-2]
J8  XT30PW-F  [AMASS_XT30PW-F]
J9  XT30PW-F  [AMASS_XT30PW-F]
J10  XT30PW-F  [AMASS_XT30PW-F]
J11  XT30PW-F  [AMASS_XT30PW-F]
J12  XT30PW-F  [AMASS_XT30PW-F]
J13  XT30PW-F  [AMASS_XT30PW-F]
J14  XT30PW-F  [AMASS_XT30PW-F]
J15  XT30PW-F  [AMASS_XT30PW-F]
J16  XT30PW-F  [AMASS_XT30PW-F]
J17  XT30PW-F  [AMASS_XT30PW-F]
J18  XT30PW-F  [AMASS_XT30PW-F]
J19  XT30PW-F  [AMASS_XT30PW-F]
J20  XT30PW-F  [AMASS_XT30PW-F]
J21  XT30PW-F  [AMASS_XT30PW-F]
J22  XT30PW-F  [AMASS_XT30PW-F]
J23  S93515  [CONN16_S93515_WRE]
J24  S93515  [CONN16_S93515_WRE]
J25  S93515  [CONN16_S93515_WRE]
J26  S93515  [CONN16_S93515_WRE]
R31  value 1.6k  [FP-RMCF0603-MFG]  (hidden comment: RMCF0603JT1K60)
R32  value 1.6k  [FP-RMCF0603-MFG]  (hidden comment: RMCF0603JT1K60)
R33  value 1.6k  [FP-RMCF0603-MFG]  (hidden comment: RMCF0603JT1K60)
R34  value 1.6k  [FP-RMCF0603-MFG]  (hidden comment: RMCF0603JT1K60)
R35  value 1.6k  [FP-RMCF0603-MFG]  (hidden comment: RMCF0603JT1K60)
R36  value 1.6k  [FP-RMCF0603-MFG]  (hidden comment: RMCF0603JT1K60)
R37  value 1.6k  [FP-RMCF0603-MFG]  (hidden comment: RMCF0603JT1K60)
R38  value 1k  [RESC1608X55X25ML10T15]  (hidden comment: RT0603BRE071KL)
R39  value 1k  [RESC1608X55X25ML10T15]  (hidden comment: RT0603BRE071KL)
R40  value 1k  [RESC1608X55X25ML10T15]  (hidden comment: RT0603BRE071KL)
R41  value 1k  [RESC1608X55X25ML10T15]  (hidden comment: RT0603BRE071KL)
R42  value 1k  [RESC1608X55X25ML10T15]  (hidden comment: RT0603BRE071KL)
R43  value 1k  [RESC1608X55X25ML10T15]  (hidden comment: RT0603BRE071KL)
R44  value 1k  [RESC1608X55X25ML10T15]  (hidden comment: RT0603BRE071KL)
R45  value 1k  [RESC1608X55X25ML10T15]  (hidden comment: RT0603BRE071KL)
U4  SDT30B100D1-13  [TO252_DIO]  (value not drawn)
U5  SDT30B100D1-13  [TO252_DIO]  (value not drawn)
U6  SDT30B100D1-13  [TO252_DIO]  (value not drawn)
U7  SDT30B100D1-13  [TO252_DIO]  (value not drawn)
U8  SDT30B100D1-13  [TO252_DIO]  (value not drawn)
U9  SDT30B100D1-13  [TO252_DIO]  (value not drawn)
U10  SDT30B100D1-13  [TO252_DIO]  (value not drawn)
U11  SDT30B100D1-13  [TO252_DIO]  (value not drawn)
U12  SDT30B100D1-13  [TO252_DIO]  (value not drawn)
U13  SDT30B100D1-13  [TO252_DIO]  (value not drawn)
U14  SDT30B100D1-13  [TO252_DIO]  (value not drawn)
U15  SDT30B100D1-13  [TO252_DIO]  (value not drawn)
U16  SDT30B100D1-13  [TO252_DIO]  (value not drawn)
U17  SDT30B100D1-13  [TO252_DIO]  (value not drawn)
U18  SDT30B100D1-13  [TO252_DIO]  (value not drawn)

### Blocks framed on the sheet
Software Compute Connectors: D4 D5 F4 F5 J8 J9 R31 R32 U4 U5
18V Spare Connectors: D6-D10 F6-F10 J10-J14 R33-R37 U6-U10
Software USB Hub & PTZ Camera: D11 D12 F11 F12 J15 J16 R38 R39 U11 U12
Science Linear Actuator, Vacuum Pump, NPK Probe: D13 D14 F13 F14 J17 J18 R40 R41 U13 U14
Chassis Fans: D15 F15 J19 R42 U15
12V Spare Connectors: D16-D18 F16-F18 J20-J22 R43-R45 U16-U18

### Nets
12V_Fans: F15.2_1 F15.2_2 J19.P R42.2 U15.3(K)
12V_PTZ: F12.2_1 F12.2_2 J16.P R39.2 U12.3(K)
12V_RoverLab1: F13.2_1 F13.2_2 J17.P R40.2 U13.3(K)
12V_RoverLab2: F14.2_1 F14.2_2 J18.P R41.2 U14.3(K)
12V_S: F11.1_1 F11.1_2 F12.1_1 F12.1_2 F13.1_1 F13.1_2 F14.1_1 F14.1_2 F15.1_1 F15.1_2 F16.1_1 F16.1_2 F17.1_1 F17.1_2 F18.1_1 F18.1_2
12V_Spare1: F16.2_1 F16.2_2 J20.P R43.2 U16.3(K)
12V_Spare2: F17.2_1 F17.2_2 J21.P R44.2 U17.3(K)
12V_Spare3: F18.2_1 F18.2_2 J22.P R45.2 U18.3(K)
12V_USB_HUB: F11.2_1 F11.2_2 J15.P R38.2 U11.3(K)
18V_JETSON: F5.2_1 F5.2_2 J9.P R32.2 U5.3(K)
18V_NUC: F4.2_1 F4.2_2 J8.P R31.2 U4.3(K)
18V_S: F4.1_1 F4.1_2 F5.1_1 F5.1_2 F6.1_1 F6.1_2 F7.1_1 F7.1_2 F8.1_1 F8.1_2 F9.1_1 F9.1_2 F10.1_1 F10.1_2
18V_Spare1: F6.2_1 F6.2_2 J10.P R33.2 U6.3(K)
18V_Spare2: F7.2_1 F7.2_2 J11.P R34.2 U7.3(K)
18V_Spare3: F8.2_1 F8.2_2 J12.P R35.2 U8.3(K)
18V_Spare4: F9.2_1 F9.2_2 J13.P R36.2 U9.3(K)
18V_Spare5: F10.2_1 F10.2_2 J14.P R37.2 U10.3(K)
24V: J23.1 J23.2 J23.3 J23.4 J23.5 J23.6 J23.7 J23.8 J23.9 J23.10 J23.11 J23.12 J23.13 J23.14 J23.15 J23.16 J25.1 J25.2 J25.3 J25.4 J25.5 J25.6 J25.7 J25.8 J25.9 J25.10 J25.11 J25.12 J25.13 J25.14 J25.15 J25.16
GND: D4.1(K) D5.1(K) D6.1(K) D7.1(K) D8.1(K) D9.1(K) D10.1(K) D11.1(K) D12.1(K) D13.1(K) D14.1(K) D15.1(K) D16.1(K) D17.1(K) D18.1(K) J8.N J9.N J10.N J11.N J12.N J13.N J14.N J15.N J16.N J17.N J18.N J19.N J20.N J21.N J22.N J24.1 J24.2 J24.3 J24.4 J24.5 J24.6 J24.7 J24.8 J24.9 J24.10 J24.11 J24.12 J24.13 J24.14 J24.15 J24.16 J26.1 J26.2 J26.3 J26.4 J26.5 J26.6 J26.7 J26.8 J26.9 J26.10 J26.11 J26.12 J26.13 J26.14 J26.15 J26.16 U4.1(A) U4.2(A) U5.1(A) U5.2(A) U6.1(A) U6.2(A) U7.1(A) U7.2(A) U8.1(A) U8.2(A) U9.1(A) U9.2(A) U10.1(A) U10.2(A) U11.1(A) U11.2(A) U12.1(A) U12.2(A) U13.1(A) U13.2(A) U14.1(A) U14.2(A) U15.1(A) U15.2(A) U16.1(A) U16.2(A) U17.1(A) U17.2(A) U18.1(A) U18.2(A)
NetD4_2: D4.2(A) R31.1
NetD5_2: D5.2(A) R32.1
NetD6_2: D6.2(A) R33.1
NetD7_2: D7.2(A) R34.1
NetD8_2: D8.2(A) R35.1
NetD9_2: D9.2(A) R36.1
NetD10_2: D10.2(A) R37.1
NetD11_2: D11.2(A) R38.1
NetD12_2: D12.2(A) R39.1
NetD13_2: D13.2(A) R40.1
NetD14_2: D14.2(A) R41.1
NetD15_2: D15.2(A) R42.1
NetD16_2: D16.2(A) R43.1
NetD17_2: D17.2(A) R44.1
NetD18_2: D18.2(A) R45.1

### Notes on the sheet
- (near U4) DNP
- (near U5) DNP
- (near U6) DNP
- (near U7) DNP
- (near U8) DNP
- (near U9) DNP
- (near U10) DNP
- (near U11) DNP
- (near U16) DNP
- (near U17) DNP
- (near U18) DNP

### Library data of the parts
D4-D18 = CMP-007-00044-1: as D1 on sheet PDB_18V_12V_Power
F4-F18 = CMP-005-00014-1: as F1 on sheet PDB_18V_12V_Power
J8-J22 = CMP-002-00091-1: Socket; DC supply; XT30; female; PIN: 2; on PCBs; THT; yellow; 15A; MF: amass
J23-J26 = CMP-083-000000-2: Description; Manufacturer_Name: Wurth Electronics
R31-R37 = CMP-009-00285-1: as R6 on sheet PDB_18V_12V_Power
R38-R45 = CMP-009-00263-1: as R20 on sheet PDB_18V_12V_Power
U4-U18 = CMP-004-00037-2: Description; Manufacturer_Name: Diodes Inc

## Sheet PDB_18V_12V_MCU_Peripherals.SchDoc
size A3
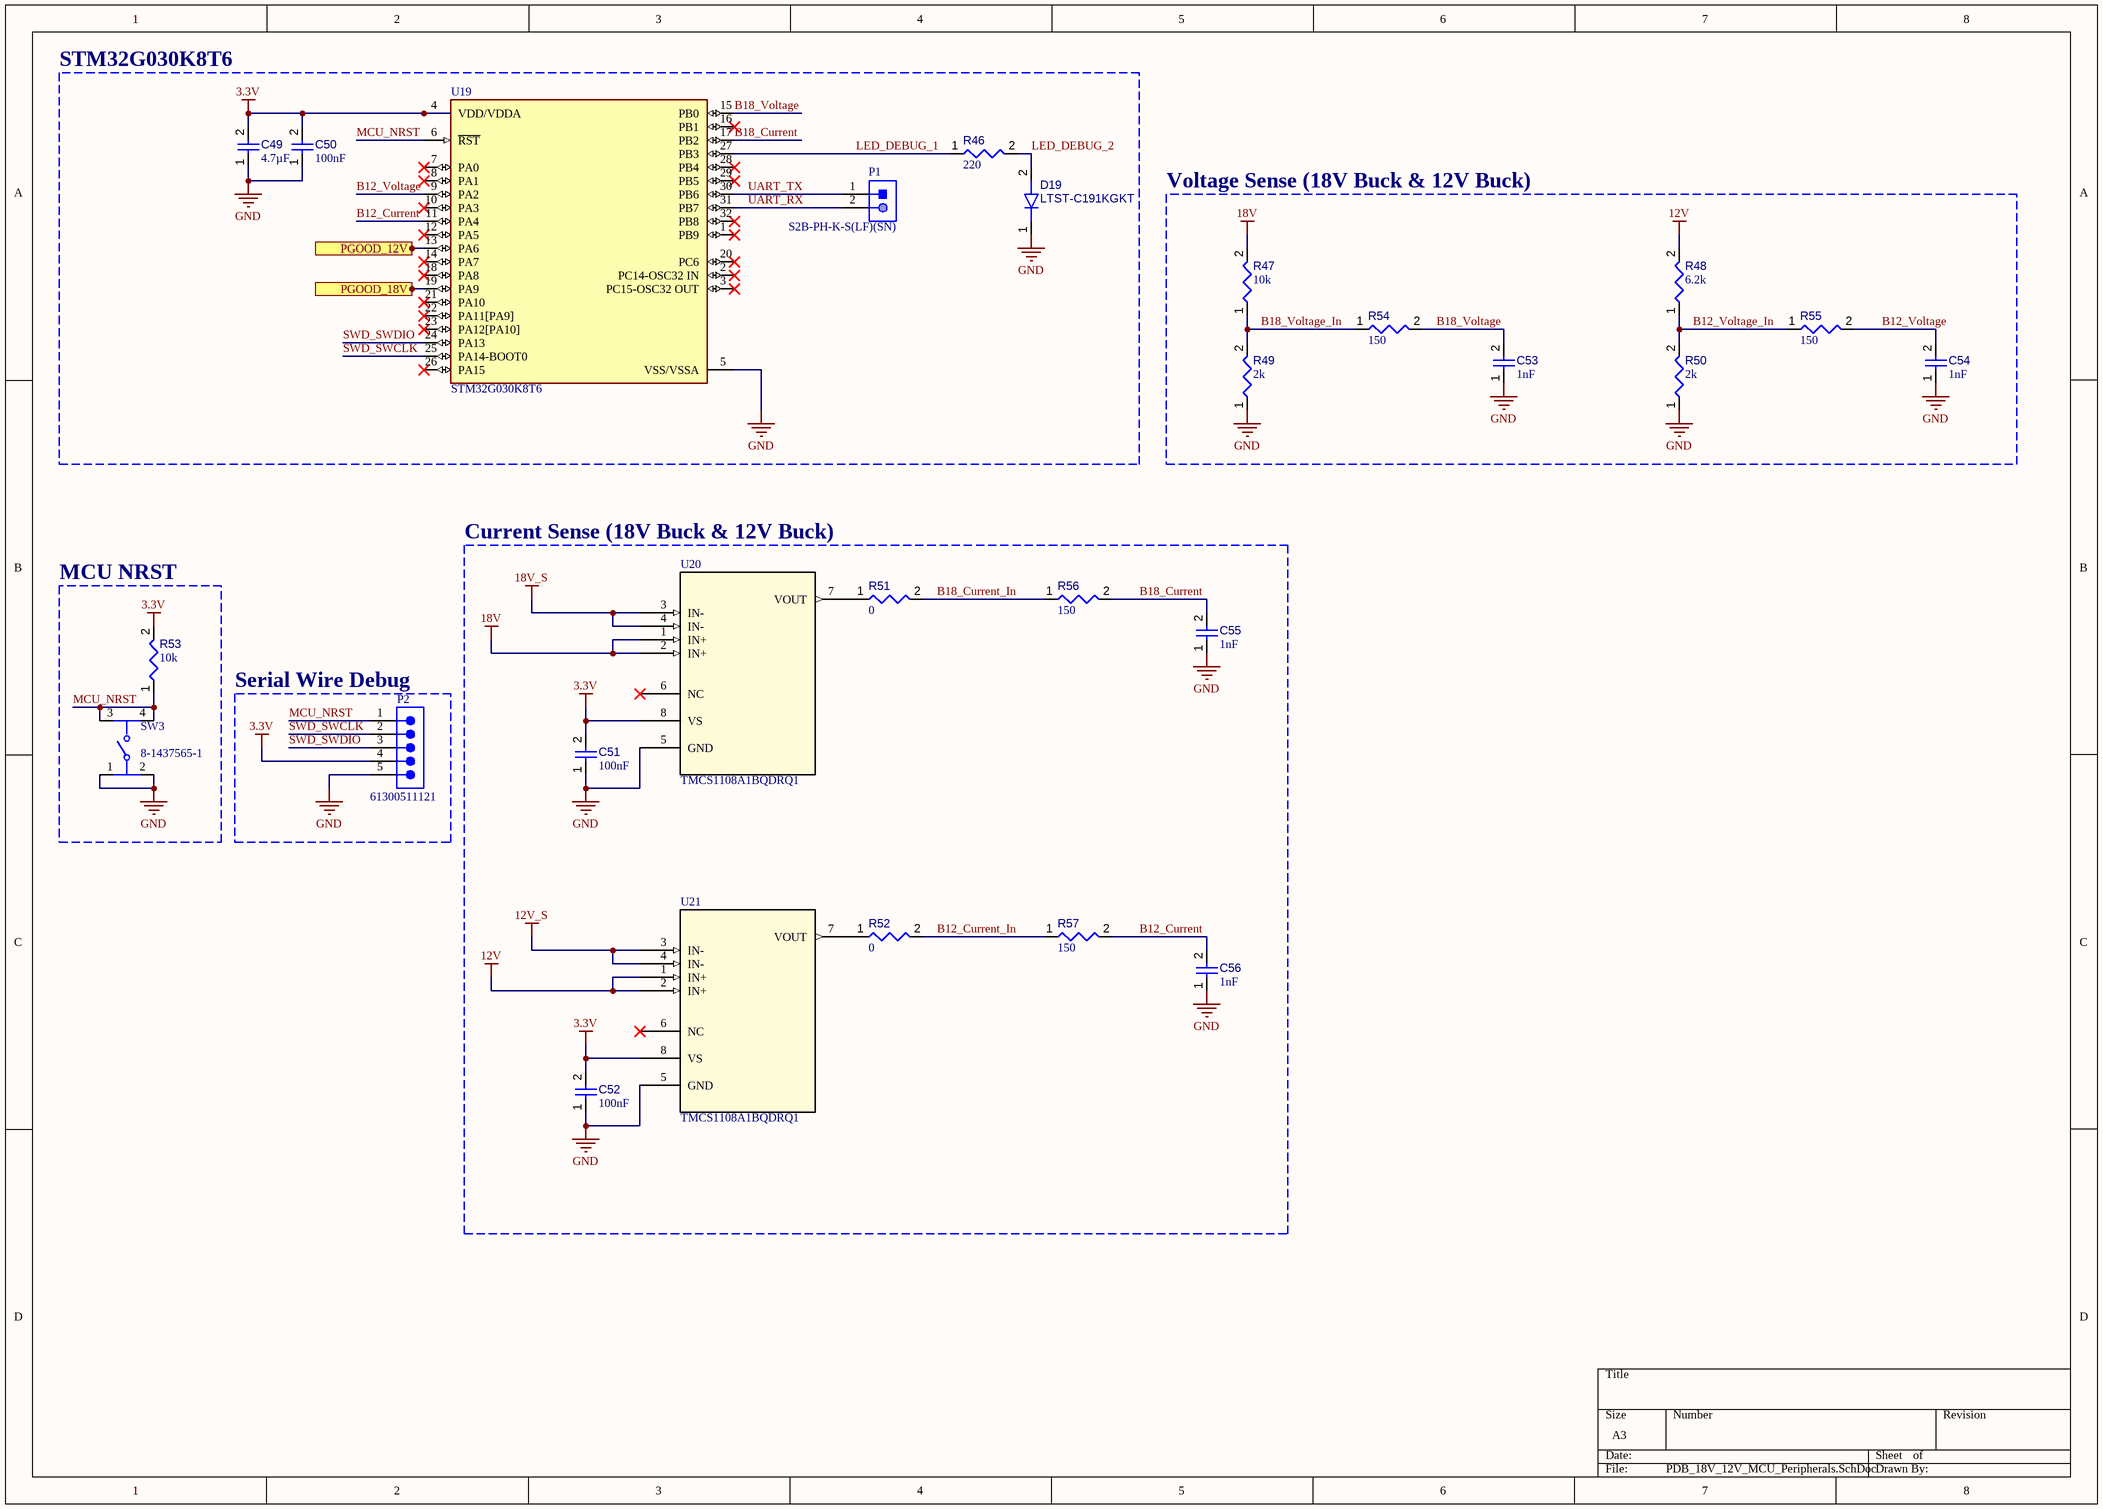
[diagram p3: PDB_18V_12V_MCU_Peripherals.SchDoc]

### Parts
C49  value 4.7µF  [FP-GRM188-0_15-MFG]  (hidden comment: GRM188R61E475KE11D)
C50  value 100nF  [FP-CL830-IPC_C]  (hidden comment: CL05B104KA5NNNC)
C51  value 100nF  [FP-CL830-IPC_C]  (hidden comment: CL05B104KA5NNNC)
C52  value 100nF  [FP-CL830-IPC_C]  (hidden comment: CL05B104KA5NNNC)
C53  value 1nF  [FP-GRM155-0_05-MFG]  (hidden comment: GRM1555C1H102JA01D)
C54  value 1nF  [FP-GRM155-0_05-MFG]  (hidden comment: GRM1555C1H102JA01D)
C55  value 1nF  [FP-GRM155-0_05-MFG]  (hidden comment: GRM1555C1H102JA01D)
C56  value 1nF  [FP-GRM155-0_05-MFG]  (hidden comment: GRM1555C1H102JA01D)
D19  LTST-C191KGKT  [FP-LTST-C191KGKT-MFG]
P1  S2B-PH-K-S(LF)(SN)  [JST-S2B-PH-K-S_V]
P2  61300511121  [61300511121]
R46  value 220  [FP-CRGCQ0603-IPC_C]  (hidden comment: CRGCQ0603J220R)
R47  value 10k  [FP-RC0603-0_55-MFG]  (hidden comment: RC0603FR-0710KL)
R48  value 6.2k  [RESC1608X55X25LL10T15]  (hidden comment: RC0603JR-076K2L)
R49  value 2k  [RESC1608X55X30LL15T15]  (hidden comment: ERJ-3EKF2001V)
R50  value 2k  [RESC1608X55X30LL15T15]  (hidden comment: ERJ-3EKF2001V)
R51  value 0  [FP-RMCF0603-IPC_A]  (hidden comment: RMCF0603ZT0R00)
R52  value 0  [FP-RMCF0603-IPC_A]  (hidden comment: RMCF0603ZT0R00)
R53  value 10k  [FP-RC0603-0_55-MFG]  (hidden comment: RC0603FR-0710KL)
R54  value 150  [RESC1005X40X25LL05T10]  (hidden comment: RC0402FR-07150RL)
R55  value 150  [RESC1005X40X25LL05T10]  (hidden comment: RC0402FR-07150RL)
R56  value 150  [RESC1005X40X25LL05T10]  (hidden comment: RC0402FR-07150RL)
R57  value 150  [RESC1005X40X25LL05T10]  (hidden comment: RC0402FR-07150RL)
SW3  8-1437565-1  [FP-8-1437565-1-MFG]
U19  STM32G030K8T6  [FP-LQFP32-5V-MFG]
U20  TMCS1108A1BQDRQ1  [SOIC8_D_TEX]
U21  TMCS1108A1BQDRQ1  [SOIC8_D_TEX]

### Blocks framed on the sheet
STM32G030K8T6: C49 C50 D19 P1 R46 U19
Voltage Sense (18V Buck & 12V Buck): C53 C54 R47-R50 R54 R55
Current Sense (18V Buck & 12V Buck): C51 C52 C55 C56 R51 R52 R56 R57 U20 U21
MCU NRST: R53 SW3
Serial Wire Debug: P2

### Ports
PGOOD_12V (in), PGOOD_18V (in)

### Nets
3.3V: C49.2 C50.2 C51.2 C52.2 P2.4 R53.2 U19.4(VDD/VDDA) U20.8(VS) U21.8(VS)
12V: R48.2 U21.1(IN+) U21.2(IN+)
12V_S: U21.3(IN-) U21.4(IN-)
18V: R47.2 U20.1(IN+) U20.2(IN+)
18V_S: U20.3(IN-) U20.4(IN-)
GND: C49.1 C50.1 C51.1 C52.1 C53.1 C54.1 C55.1 C56.1 D19.1(K) P2.5 R49.1 R50.1 SW3.1 SW3.2 U19.5(VSS/VSSA) U20.5(GND) U21.5(GND)
B12_Current: C56.2 R57.2 U19.11(PA4)
B12_Current_In: R52.2 R57.1
B12_Voltage: C54.2 R55.2 U19.9(PA2)
B12_Voltage_In: R48.1 R50.2 R55.1
B18_Current: C55.2 R56.2 U19.17(PB2)
B18_Current_In: R51.2 R56.1
B18_Voltage: C53.2 R54.2 U19.15(PB0)
B18_Voltage_In: R47.1 R49.2 R54.1
LED_DEBUG_1: R46.1 U19.27(PB3)
LED_DEBUG_2: D19.2(A) R46.2
MCU_NRST: P2.1 R53.1 SW3.3 SW3.4 U19.6(~{RST})
PGOOD_12V: U19.13(PA6) ; port PGOOD_12V
PGOOD_18V: U19.19(PA9) ; port PGOOD_18V
SWD_SWCLK: P2.2 U19.25(PA14-BOOT0)
SWD_SWDIO: P2.3 U19.24(PA13)
UART_RX: P1.2 U19.31(PB7)
UART_TX: P1.1 U19.30(PB6)
NetR51_1: R51.1 U20.7(VOUT)
NetR52_1: R52.1 U21.7(VOUT)

Not connected (* = marked no-connect by the designer): U19 1(PB9)* 2(PC14-OSC32_IN)* 3(PC15-OSC32_OUT)* 7(PA0)* 8(PA1)* 10(PA3)* 12(PA5)* 14(PA7)* 16(PB1)* 18(PA8)* 20(PC6)* 21(PA10)* 22(PA11[PA9])* 23(PA12[PA10])* 26(PA15)* 28(PB4)* 29(PB5)* 32(PB8)*; U20 6(NC)*; U21 6(NC)*

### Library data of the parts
C49 = CMP-001-00175-1: 25V 4.7uF X5R ±10% 0603 Multilayer Ceramic Capacitors MLCC - SMD/SMT ROHS
C50-C52 = CMP-001-00174-1: 25V 100nF X7R 卤10% 0402 Multilayer Ceramic Capacitors MLCC - SMD/SMT ROHS; Tolerance: 10%
C53-C56 = CMP-001-00142-1: Ceramic Capacitor, Multilayer, Ceramic, 50V, 5% +Tol, 5% -Tol, C0G, 30ppm/Cel TC, 0.001uF, Surface Mount, 0402
D19 = CMP-004-00036-1: LED yellow green 0603 wavelength 567.5~576.5nm light intensity 18~71mcd Front Mounting; Forward Voltage: 2.4V; Forward Current: 30mA
P1 = CMP-002-00030-2: Male Header, Pitch 2 mm, 1 x 2 Position, Height 4.8 mm, Tail Length 3.4 mm, -25 to 85 degC, RoHS, Bulk; Manufacturer: Japan Solderless Terminals
P2 = CMP-002-00093-1: WR-PHD Straight Male, PCB Header, Through Hole, 1 Rows, 5 Contacts, 2.54mm Pitch; Connector Type: Male Pin; Voltage Rating: 250V
R46 = CMP-009-00289-1: Res Thick Film 0603 220 Ohm 5% 0.1W(1/10W) ±100ppm/C Pad SMD Automotive T/R; Voltage Rating: 75V
R47 R53 = CMP-009-00288-1: 100mW Thick Film Resistors ±100ppm/℃ ±1% 10kΩ 0603 Chip Resistor - Surface Mount ROHS; Voltage Rating: 75V
R48 = CMP-009-00294-1: 100mW Thick Film Resistors 75V ±100ppm/℃ ±5% 6.2kΩ 0603 Chip Resistor - Surface Mount ROHS; Voltage Rating: 50V
R49 R50 = CMP-009-00293-1: Res Thick Film 0603 2K Ohm 1% 1/10W ±100ppm/°C Molded SMD Punched Carrier T/R; Voltage Rating: 75V
R51 R52 = CMP-009-00236-1: as R1 on sheet PDB_18V_12V_Power
R54-R57 = CMP-009-00298-1: Yageo RC0402FR-07150RL Resistor 0603 SMD 150 Ohm precision thick film; Voltage Rating: 50V; Tolerance: 1%
SW3 = CMP-011-00018-1: Switch Tactile OFF (ON) SPST Round Button Gull Wing 0.05A 24VDC 2.55N SMD T/R; Max Current Rating: 20mA
U19 = CMP-020-00027-1: Microcontroller 32-bit ARM Cortex-M0+ RISC 64KB Flash 3.3V 32-Pin LQFP Tray; Frequency: 64MHz; Min Supply Voltage: 2V; Clock Frequency: 48MHz; RAM Size: 8kB; Max Supply Voltage: 3.6V; Interface: I2S
U20 U21 = CMP-056-000000-1: AEC-Q100, Â±100-V isolated Hall-effect current sensor with internal reference 8-SOIC -40 to 125; Manufacturer_Name: Texas Instruments

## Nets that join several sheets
3.3V: PDB_18V_12V_Power (8 pins), PDB_18V_12V_MCU_Peripherals (9 pins)
12V: PDB_18V_12V_Power (12 pins), PDB_18V_12V_MCU_Peripherals (R48.2 U21.1 U21.2)
12V_S: PDB_18V_12V_Power (J3.1), PDB_18V_12V_Connectors (16 pins), PDB_18V_12V_MCU_Peripherals (U21.3 U21.4)
18V: PDB_18V_12V_Power (12 pins), PDB_18V_12V_MCU_Peripherals (R47.2 U20.1 U20.2)
18V_S: PDB_18V_12V_Power (J6.1), PDB_18V_12V_Connectors (14 pins), PDB_18V_12V_MCU_Peripherals (U20.3 U20.4)
24V: PDB_18V_12V_Power (7 pins), PDB_18V_12V_Connectors (32 pins)
GND: PDB_18V_12V_Power (69 pins), PDB_18V_12V_Connectors (92 pins), PDB_18V_12V_MCU_Peripherals (17 pins)
PGOOD_12V: PDB_18V_12V_Power (R24.1 U3.10), PDB_18V_12V_MCU_Peripherals (U19.13)
PGOOD_18V: PDB_18V_12V_Power (R11.1 U2.10), PDB_18V_12V_MCU_Peripherals (U19.19)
